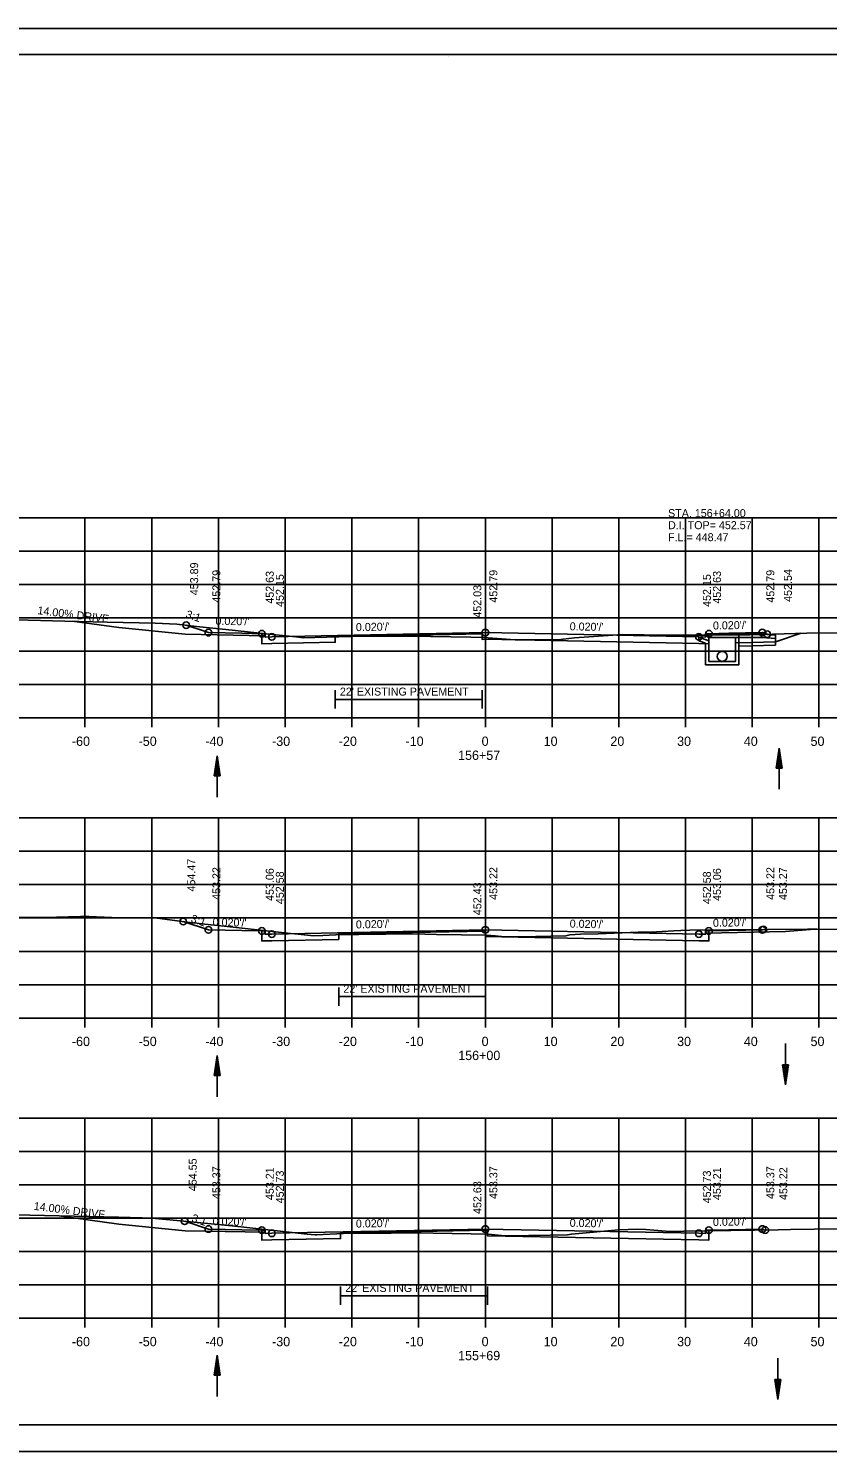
# Model space of a CAD drawing. Extents: x 1538688 to 1540766, y 656250 to 671912.
# Drawn here: x 1538789.7 to 1538909.5, y 666151.4 to 666364.8 of the extents above; entities that cross this region are included whole.
import ezdxf

# ---------------------------------------------------------------- set-up
doc = ezdxf.new("R2010")
doc.units = 0
for name, color, linetype in [('15', 7, 'Continuous'), ('16', 7, 'Continuous'), ('18', 7, 'Continuous'), ('20', 7, 'Continuous'), ('22', 7, 'Continuous'), ('26', 7, 'Continuous'), ('39', 7, 'Continuous'), ('40', 7, 'Continuous'), ('41', 7, 'Continuous'), ('42', 7, 'Continuous'), ('7', 7, 'Continuous'), ('Borings', 7, 'Continuous'), ('Horizontal Alignment', 7, 'Continuous'), ('RipRap', 7, 'Continuous'), ('Wall Heights', 7, 'Continuous')]:
    doc.layers.add(name, color=color, linetype=linetype)

msp = doc.modelspace()

# ---------------------------------------------------------------- linework, layer by layer
at = {"layer": '15'}
for p, q in [((1538817.56, 666252.74), (1538818.01, 666255.74)), ((1538818.46, 666252.74), (1538818.01, 666255.74)), ((1538901.74, 666253.91), (1538902.19, 666256.91)), ((1538901.82, 666253.91), (1538902.19, 666256.41)), ((1538901.89, 666253.91), (1538902.19, 666255.89)), ((1538902.64, 666253.91), (1538902.19, 666256.91)), ((1538902.57, 666253.91), (1538902.19, 666256.41)), ((1538902.49, 666253.91), (1538902.19, 666255.89)), ((1538817.64, 666252.74), (1538818.01, 666255.24)), ((1538817.71, 666252.74), (1538818.01, 666254.72)), ((1538817.79, 666252.74), (1538818.01, 666254.22)), ((1538817.87, 666252.74), (1538818.01, 666253.71)), ((1538818.39, 666252.74), (1538818.01, 666255.24)), ((1538818.31, 666252.74), (1538818.01, 666254.72)), ((1538818.23, 666252.74), (1538818.01, 666254.22)), ((1538818.16, 666252.74), (1538818.01, 666253.71)), ((1538901.74, 666253.91), (1538902.64, 666253.91)), ((1538901.97, 666253.91), (1538902.19, 666255.39)), ((1538902.05, 666253.91), (1538902.19, 666254.88)), ((1538902.12, 666253.91), (1538902.19, 666254.38)), ((1538902.42, 666253.91), (1538902.19, 666255.39)), ((1538902.34, 666253.91), (1538902.19, 666254.88)), ((1538902.26, 666253.91), (1538902.19, 666254.38)), ((1538817.56, 666252.74), (1538818.46, 666252.74)), ((1538817.94, 666252.74), (1538818.01, 666253.21)), ((1538818.08, 666252.74), (1538818.01, 666253.21)), ((1538817.56, 666207.82), (1538818.01, 666210.82)), ((1538818.46, 666207.82), (1538818.01, 666210.82)), ((1538817.64, 666207.82), (1538818.01, 666210.32)), ((1538817.71, 666207.82), (1538818.01, 666209.8)), ((1538817.79, 666207.82), (1538818.01, 666209.3)), ((1538817.87, 666207.82), (1538818.01, 666208.79)), ((1538818.39, 666207.82), (1538818.01, 666210.32)), ((1538818.31, 666207.82), (1538818.01, 666209.8)), ((1538818.23, 666207.82), (1538818.01, 666209.3)), ((1538818.16, 666207.82), (1538818.01, 666208.79)), ((1538902.69, 666209.42), (1538903.14, 666206.42)), ((1538903.59, 666209.42), (1538902.69, 666209.42)), ((1538902.76, 666209.42), (1538903.14, 666206.92)), ((1538902.84, 666209.42), (1538903.14, 666207.43)), ((1538902.92, 666209.42), (1538903.14, 666207.93)), ((1538902.99, 666209.42), (1538903.14, 666208.44)), ((1538903.07, 666209.42), (1538903.14, 666208.94)), ((1538903.59, 666209.42), (1538903.14, 666206.42)), ((1538903.28, 666209.42), (1538903.14, 666208.44)), ((1538903.44, 666209.42), (1538903.14, 666207.43)), ((1538903.51, 666209.42), (1538903.14, 666206.92)), ((1538903.36, 666209.42), (1538903.14, 666207.93)), ((1538903.21, 666209.42), (1538903.14, 666208.94)), ((1538817.56, 666207.82), (1538818.46, 666207.82)), ((1538817.94, 666207.82), (1538818.01, 666208.29)), ((1538818.08, 666207.82), (1538818.01, 666208.29)), ((1538817.56, 666162.9), (1538818.01, 666165.9)), ((1538818.46, 666162.9), (1538818.01, 666165.9)), ((1538817.64, 666162.9), (1538818.01, 666165.4)), ((1538817.71, 666162.9), (1538818.01, 666164.88)), ((1538817.79, 666162.9), (1538818.01, 666164.38)), ((1538817.87, 666162.9), (1538818.01, 666163.87)), ((1538818.39, 666162.9), (1538818.01, 666165.4)), ((1538818.31, 666162.9), (1538818.01, 666164.88)), ((1538818.23, 666162.9), (1538818.01, 666164.38)), ((1538818.16, 666162.9), (1538818.01, 666163.87)), ((1538817.56, 666162.9), (1538818.46, 666162.9)), ((1538817.94, 666162.9), (1538818.01, 666163.37)), ((1538818.08, 666162.9), (1538818.01, 666163.37)), ((1538901.54, 666162.26), (1538901.99, 666159.26)), ((1538902.44, 666162.26), (1538901.54, 666162.26)), ((1538901.62, 666162.26), (1538901.99, 666159.76)), ((1538901.69, 666162.26), (1538901.99, 666160.28)), ((1538901.77, 666162.26), (1538901.99, 666160.78)), ((1538901.85, 666162.26), (1538901.99, 666161.29)), ((1538901.92, 666162.26), (1538901.99, 666161.79)), ((1538902.44, 666162.26), (1538901.99, 666159.26)), ((1538902.14, 666162.26), (1538901.99, 666161.29)), ((1538902.29, 666162.26), (1538901.99, 666160.28)), ((1538902.37, 666162.26), (1538901.99, 666159.76)), ((1538902.22, 666162.26), (1538901.99, 666160.78)), ((1538902.06, 666162.26), (1538901.99, 666161.79))]:
    msp.add_line(p, q, dxfattribs=at)
at = {"layer": '16'}
for p, q in [((1538796.26, 666275.91), (1538803.23, 666274.96)), ((1538803.23, 666274.96), (1538813.18, 666273.96)), ((1538813.18, 666273.96), (1538825.18, 666273.72)), ((1538891.18, 666229.15), (1538903.18, 666229.39)), ((1538903.18, 666229.39), (1538907.5, 666229.77)), ((1538794.33, 666186.79), (1538803.23, 666185.54)), ((1538803.23, 666185.54), (1538813.18, 666184.55)), ((1538813.18, 666184.55), (1538825.18, 666184.31))]:
    msp.add_line(p, q, dxfattribs=at)
at = {"layer": '18'}
for points in [[(1538786.01, 666276.2), (1538795.15, 666275.93), (1538801.52, 666275.78), (1538808.68, 666275.61), (1538811.95, 666275.5), (1538814.88, 666275.12), (1538819.28, 666274.69), (1538825.8, 666274), (1538829.78, 666273.58), (1538830.94, 666273.45), (1538834.35, 666273.54), (1538836.24, 666273.59), (1538837.97, 666273.61), (1538846.95, 666273.7), (1538856, 666273.51), (1538857.89, 666273.47), (1538862.67, 666273.15), (1538862.97, 666273.14), (1538866.53, 666273.12), (1538868.6, 666273.11), (1538869.14, 666273.12), (1538869.83, 666273.24), (1538871.52, 666273.42), (1538878.75, 666273.95), (1538885.25, 666273.81), (1538889.63, 666273.85), (1538890.52, 666273.81), (1538891.48, 666273.81), (1538897.83, 666273.9), (1538906.37, 666274.14), (1538918.13, 666274.18)], [(1538782.15, 666231.6), (1538792.09, 666231.51), (1538797.51, 666231.64), (1538798.77, 666231.63), (1538803.36, 666231.45), (1538808.26, 666231.49), (1538813.12, 666230.87), (1538814.23, 666230.72), (1538814.92, 666230.66), (1538815.29, 666230.6), (1538816.14, 666230.53), (1538819.03, 666230.23), (1538828.98, 666229.13), (1538830.13, 666229), (1538832.42, 666228.74), (1538833.8, 666228.81), (1538836.73, 666228.94), (1538839.21, 666228.96), (1538847.36, 666229.04), (1538850.84, 666228.98), (1538858.33, 666228.85), (1538859.63, 666228.74), (1538861.04, 666228.61), (1538865.73, 666228.68), (1538870.24, 666228.76), (1538870.86, 666228.93), (1538872.46, 666228.99), (1538875.09, 666229.07), (1538881.1, 666229.33), (1538883.84, 666229.37), (1538886.42, 666229.5), (1538887.47, 666229.56), (1538888.84, 666229.61), (1538906.48, 666229.76), (1538906.74, 666229.77), (1538907.11, 666229.77), (1538907.93, 666229.77), (1538921.83, 666229.73)], [(1538785.4, 666186.99), (1538803.19, 666186.59), (1538806.75, 666186.5), (1538808.18, 666186.45), (1538811.92, 666186.1), (1538820.18, 666185.29), (1538831.47, 666184.04), (1538832.68, 666183.91), (1538832.85, 666183.92), (1538836.94, 666184.11), (1538844.05, 666184.19), (1538847.51, 666184.24), (1538856.03, 666184.1), (1538858.6, 666184.05), (1538860.59, 666183.85), (1538861.43, 666183.77), (1538867.89, 666183.89), (1538870.47, 666183.93), (1538871.08, 666184.04), (1538878.18, 666184.68), (1538880.98, 666184.78), (1538882.23, 666184.73), (1538885.83, 666184.41), (1538885.94, 666184.41), (1538885.96, 666184.41), (1538887.92, 666184.47), (1538902.06, 666184.68), (1538903.89, 666184.74), (1538918.12, 666184.94)]]:
    msp.add_lwpolyline(points, dxfattribs=at)
at = {"layer": '20'}
for points in [[(1538813.34, 666275.32), (1538816.67, 666274.21), (1538821.67, 666274.11), (1538824.67, 666274.05), (1538825.17, 666274.05), (1538825.18, 666273.55), (1538826.18, 666273.57), (1538858.18, 666274.21), (1538890.18, 666273.57), (1538891.18, 666273.55), (1538891.19, 666274.05), (1538891.69, 666274.05), (1538894.69, 666274.11), (1538899.69, 666274.21), (1538900.42, 666273.97)], [(1538812.9, 666230.9), (1538816.67, 666229.65), (1538821.67, 666229.55), (1538824.67, 666229.49), (1538825.17, 666229.49), (1538825.18, 666228.99), (1538826.18, 666229.01), (1538858.18, 666229.65), (1538890.18, 666229.01), (1538891.18, 666228.99), (1538891.19, 666229.49), (1538891.69, 666229.49), (1538894.69, 666229.55), (1538899.69, 666229.65), (1538899.86, 666229.7)], [(1538813.12, 666185.98), (1538816.67, 666184.8), (1538821.67, 666184.7), (1538824.67, 666184.64), (1538825.17, 666184.64), (1538825.18, 666184.14), (1538826.18, 666184.16), (1538858.18, 666184.8), (1538890.18, 666184.16), (1538891.18, 666184.14), (1538891.19, 666184.64), (1538891.69, 666184.64), (1538894.69, 666184.7), (1538899.69, 666184.8), (1538900.13, 666184.65)]]:
    msp.add_lwpolyline(points, dxfattribs=at)
at = {"layer": '22'}
for p, q in [((1538718.18, 666291.43), (1538998.18, 666291.43)), ((1538798.18, 666261.43), (1538798.18, 666291.43)), ((1538808.18, 666261.43), (1538808.18, 666291.43)), ((1538818.18, 666261.43), (1538818.18, 666291.43)), ((1538828.18, 666261.43), (1538828.18, 666291.43)), ((1538838.18, 666261.43), (1538838.18, 666291.43)), ((1538848.18, 666261.43), (1538848.18, 666291.43)), ((1538858.18, 666261.43), (1538858.18, 666291.43)), ((1538868.18, 666261.43), (1538868.18, 666291.43)), ((1538878.18, 666261.43), (1538878.18, 666291.43)), ((1538888.18, 666261.43), (1538888.18, 666291.43)), ((1538898.18, 666261.43), (1538898.18, 666291.43)), ((1538908.18, 666261.43), (1538908.18, 666291.43)), ((1538718.18, 666286.43), (1538998.18, 666286.43)), ((1538718.18, 666281.43), (1538998.18, 666281.43)), ((1538718.18, 666276.43), (1538998.18, 666276.43)), ((1538718.18, 666271.43), (1538998.18, 666271.43)), ((1538718.18, 666266.43), (1538998.18, 666266.43)), ((1538718.18, 666261.43), (1538998.18, 666261.43)), ((1538718.18, 666246.43), (1538998.18, 666246.43)), ((1538798.18, 666216.43), (1538798.18, 666246.43)), ((1538808.18, 666216.43), (1538808.18, 666246.43)), ((1538818.18, 666216.43), (1538818.18, 666246.43)), ((1538828.18, 666216.43), (1538828.18, 666246.43)), ((1538838.18, 666216.43), (1538838.18, 666246.43)), ((1538848.18, 666216.43), (1538848.18, 666246.43)), ((1538858.18, 666216.43), (1538858.18, 666246.43)), ((1538868.18, 666216.43), (1538868.18, 666246.43)), ((1538878.18, 666216.43), (1538878.18, 666246.43)), ((1538888.18, 666216.43), (1538888.18, 666246.43)), ((1538898.18, 666216.43), (1538898.18, 666246.43)), ((1538908.18, 666216.43), (1538908.18, 666246.43)), ((1538718.18, 666241.43), (1538998.18, 666241.43)), ((1538718.18, 666236.43), (1538998.18, 666236.43)), ((1538718.18, 666231.43), (1538998.18, 666231.43)), ((1538718.18, 666226.43), (1538998.18, 666226.43)), ((1538718.18, 666221.43), (1538998.18, 666221.43)), ((1538718.18, 666216.43), (1538998.18, 666216.43)), ((1538718.18, 666201.43), (1538998.18, 666201.43)), ((1538798.18, 666171.43), (1538798.18, 666201.43)), ((1538808.18, 666171.43), (1538808.18, 666201.43)), ((1538818.18, 666171.43), (1538818.18, 666201.43)), ((1538828.18, 666171.43), (1538828.18, 666201.43)), ((1538838.18, 666171.43), (1538838.18, 666201.43)), ((1538848.18, 666171.43), (1538848.18, 666201.43)), ((1538858.18, 666171.43), (1538858.18, 666201.43)), ((1538868.18, 666171.43), (1538868.18, 666201.43)), ((1538878.18, 666171.43), (1538878.18, 666201.43)), ((1538888.18, 666171.43), (1538888.18, 666201.43)), ((1538898.18, 666171.43), (1538898.18, 666201.43)), ((1538908.18, 666171.43), (1538908.18, 666201.43)), ((1538718.18, 666196.43), (1538998.18, 666196.43)), ((1538718.18, 666191.43), (1538998.18, 666191.43)), ((1538718.18, 666186.43), (1538998.18, 666186.43)), ((1538718.18, 666181.43), (1538998.18, 666181.43)), ((1538718.18, 666176.43), (1538998.18, 666176.43)), ((1538718.18, 666171.43), (1538998.18, 666171.43))]:
    msp.add_line(p, q, dxfattribs=at)
at = {"layer": '26'}
for p, q in [((1538687.78, 666364.78), (1539021.11, 666364.78)), ((1538687.78, 666151.45), (1539021.11, 666151.45))]:
    msp.add_line(p, q, dxfattribs=at)
msp.add_lwpolyline([(1538687.77, 666364.78), (1539021.11, 666364.78), (1539021.11, 666151.45), (1538687.77, 666151.45)], close=True, dxfattribs=at)
for centre in [(1538813.34, 666275.32), (1538816.67, 666274.21), (1538858.18, 666274.21), (1538899.69, 666274.21), (1538824.67, 666274.05), (1538826.18, 666273.57), (1538890.18, 666273.57), (1538891.69, 666274.05), (1538900.42, 666273.97), (1538812.9, 666230.9), (1538816.67, 666229.65), (1538824.67, 666229.49), (1538858.18, 666229.65), (1538891.69, 666229.49), (1538899.69, 666229.65), (1538899.86, 666229.7), (1538826.18, 666229.01), (1538890.18, 666229.01), (1538813.12, 666185.98), (1538816.67, 666184.8), (1538824.67, 666184.64), (1538858.18, 666184.8), (1538891.69, 666184.64), (1538899.69, 666184.8), (1538900.13, 666184.65), (1538826.18, 666184.16), (1538890.18, 666184.16)]:
    msp.add_circle(centre, 0.5, dxfattribs=at)
at = {"layer": '39'}
for p, q in [((1538890.18, 666273.52), (1538891.68, 666273)), ((1538890.18, 666273.52), (1538891.68, 666273)), ((1538890.18, 666272.99), (1538891.18, 666272.64)), ((1538890.18, 666272.99), (1538891.18, 666272.64)), ((1538891.18, 666272.5), (1538891.18, 666272.64)), ((1538891.18, 666272.5), (1538891.18, 666272.64)), ((1538891.34, 666273.83), (1538891.43, 666274)), ((1538891.34, 666273.83), (1538891.43, 666274)), ((1538891.34, 666273.83), (1538891.68, 666273.5)), ((1538891.34, 666273.83), (1538891.68, 666273.5)), ((1538896.18, 666274), (1538891.43, 666274)), ((1538896.18, 666274), (1538891.43, 666274)), ((1538895.68, 666273.5), (1538891.68, 666273.5)), ((1538895.68, 666273.5), (1538891.68, 666273.5)), ((1538891.68, 666272.5), (1538891.68, 666273)), ((1538891.68, 666272.5), (1538891.68, 666273)), ((1538895.68, 666272.5), (1538895.68, 666273.5)), ((1538896.18, 666272.5), (1538896.18, 666274)), ((1538899.66, 666274), (1538901.69, 666273.85)), ((1538899.69, 666273.5), (1538901.68, 666273.35)), ((1538901.64, 666272.85), (1538905.53, 666274.14)), ((1538818.01, 666249.55), (1538818.01, 666255.74)), ((1538902.19, 666250.72), (1538902.19, 666256.91)), ((1538818.01, 666204.63), (1538818.01, 666210.82)), ((1538903.14, 666212.6), (1538903.14, 666206.42)), ((1538818.01, 666159.71), (1538818.01, 666165.9)), ((1538901.99, 666165.45), (1538901.99, 666159.26))]:
    msp.add_line(p, q, dxfattribs=at)
for points in [[(1538890.18, 666272.99), (1538890.18, 666273.52)], [(1538890.18, 666272.99), (1538890.18, 666273.52)], [(1538895.68, 666273.5), (1538898.18, 666273.5), (1538899.69, 666273.5)], [(1538895.68, 666272.66), (1538898.09, 666272.74), (1538901.64, 666272.85)], [(1538896.18, 666274), (1538898.18, 666274), (1538899.69, 666274)], [(1538896.18, 666272.18), (1538898.11, 666272.24), (1538901.66, 666272.35), (1538901.68, 666273.85)], [(1538896.18, 666272.5), (1538896.18, 666269.4), (1538893.68, 666269.4), (1538891.18, 666269.4), (1538891.18, 666272.5)], [(1538895.68, 666272.5), (1538895.68, 666269.9), (1538893.68, 666269.9), (1538891.68, 666269.9), (1538891.68, 666272.5)]]:
    msp.add_lwpolyline(points, dxfattribs=at)
msp.add_circle((1538893.68, 666270.65), 0.75, dxfattribs=at)
at = {"layer": '7'}
for p, q in [((1538835.68, 666265.59), (1538835.68, 666262.84)), ((1538857.68, 666264.21), (1538835.68, 666264.21)), ((1538857.68, 666265.59), (1538857.68, 666262.84)), ((1538836.2, 666221.03), (1538836.2, 666218.28)), ((1538858.2, 666219.66), (1538836.2, 666219.66)), ((1538858.2, 666221.03), (1538858.2, 666218.28)), ((1538836.48, 666176.19), (1538836.48, 666173.44)), ((1538858.48, 666174.81), (1538836.48, 666174.81)), ((1538858.48, 666176.19), (1538858.48, 666173.44))]:
    msp.add_line(p, q, dxfattribs=at)
at = {"layer": 'Borings'}
for p, q in [((1538718.18, 666261.43), (1538998.18, 666261.43)), ((1538798.18, 666260.03), (1538798.18, 666261.43)), ((1538808.18, 666260.03), (1538808.18, 666261.43)), ((1538818.18, 666260.03), (1538818.18, 666261.43)), ((1538828.18, 666260.03), (1538828.18, 666261.43)), ((1538838.18, 666260.03), (1538838.18, 666261.43)), ((1538848.18, 666260.03), (1538848.18, 666261.43)), ((1538858.18, 666260.03), (1538858.18, 666261.43)), ((1538868.18, 666260.03), (1538868.18, 666261.43)), ((1538878.18, 666260.03), (1538878.18, 666261.43)), ((1538888.18, 666260.03), (1538888.18, 666261.43)), ((1538898.18, 666260.03), (1538898.18, 666261.43)), ((1538908.18, 666260.03), (1538908.18, 666261.43)), ((1538718.18, 666216.43), (1538998.18, 666216.43)), ((1538798.18, 666215.03), (1538798.18, 666216.43)), ((1538808.18, 666215.03), (1538808.18, 666216.43)), ((1538818.18, 666215.03), (1538818.18, 666216.43)), ((1538828.18, 666215.03), (1538828.18, 666216.43)), ((1538838.18, 666215.03), (1538838.18, 666216.43)), ((1538848.18, 666215.03), (1538848.18, 666216.43)), ((1538858.18, 666215.03), (1538858.18, 666216.43)), ((1538868.18, 666215.03), (1538868.18, 666216.43)), ((1538878.18, 666215.03), (1538878.18, 666216.43)), ((1538888.18, 666215.03), (1538888.18, 666216.43)), ((1538898.18, 666215.03), (1538898.18, 666216.43)), ((1538908.18, 666215.03), (1538908.18, 666216.43)), ((1538718.18, 666171.43), (1538998.18, 666171.43)), ((1538798.18, 666170.03), (1538798.18, 666171.43)), ((1538808.18, 666170.03), (1538808.18, 666171.43)), ((1538818.18, 666170.03), (1538818.18, 666171.43)), ((1538828.18, 666170.03), (1538828.18, 666171.43)), ((1538838.18, 666170.03), (1538838.18, 666171.43)), ((1538848.18, 666170.03), (1538848.18, 666171.43)), ((1538858.18, 666170.03), (1538858.18, 666171.43)), ((1538868.18, 666170.03), (1538868.18, 666171.43)), ((1538878.18, 666170.03), (1538878.18, 666171.43)), ((1538888.18, 666170.03), (1538888.18, 666171.43)), ((1538898.18, 666170.03), (1538898.18, 666171.43)), ((1538908.18, 666170.03), (1538908.18, 666171.43))]:
    msp.add_line(p, q, dxfattribs=at)
at = {"layer": 'RipRap'}
for p, q in [((1538700.18, 666360.89), (1539016.36, 666360.89)), ((1538852.7, 666360.63), (1538852.7, 666360.63)), ((1538852.7, 666360.63), (1538852.7, 666360.63)), ((1539016.36, 666155.43), (1538700.18, 666155.43))]:
    msp.add_line(p, q, dxfattribs=at)
at = {"layer": 'Wall Heights'}
for points in [[(1538891.69, 666274.05), (1538891.69, 666272.55), (1538890.18, 666272.57), (1538858.18, 666273.21), (1538857.69, 666273.2), (1538857.69, 666274.04), (1538835.69, 666273.6), (1538835.69, 666272.76), (1538826.18, 666272.57), (1538824.67, 666272.55), (1538824.67, 666274.05)], [(1538891.69, 666229.49), (1538891.69, 666227.99), (1538890.18, 666228.01), (1538858.21, 666228.65), (1538858.21, 666229.48), (1538858.18, 666229.48), (1538836.21, 666229.04), (1538836.21, 666228.21), (1538826.18, 666228.01), (1538824.67, 666227.99), (1538824.67, 666229.49)], [(1538891.69, 666184.64), (1538891.69, 666183.14), (1538890.18, 666183.16), (1538858.49, 666183.79), (1538858.49, 666184.62), (1538858.18, 666184.63), (1538836.49, 666184.2), (1538836.49, 666183.37), (1538826.18, 666183.16), (1538824.67, 666183.14), (1538824.67, 666184.64)]]:
    msp.add_lwpolyline(points, dxfattribs=at)

# ---------------------------------------------------------------- texts
at = {"layer": '16'}
for p in [(1538791.01, 666276.99), (1538790.45, 666187.69)]:
    msp.add_text('14.00% DRIVE', height=1.2, rotation=352.879, dxfattribs=at).set_placement(p)
at = {"layer": '40'}
for s, p in [('STA. 156+64.00', (1538885.56, 666291.52)), ('D.I. TOP= 452.57', (1538885.56, 666289.72)), ('F.L.= 448.47', (1538885.56, 666287.92))]:
    msp.add_text(s, height=1.2, dxfattribs=at).set_placement(p)
at = {"layer": '41'}
for s, p in [('453.89', (1538815.14, 666279.82)), ('452.79', (1538818.47, 666278.71)), ('452.63', (1538826.47, 666278.55)), ('452.79', (1538859.98, 666278.71)), ('452.63', (1538893.49, 666278.55)), ('452.79', (1538901.49, 666278.71)), ('452.54', (1538904.12, 666278.82)), ('452.15', (1538827.98, 666278.07)), ('452.03', (1538857.58, 666276.45)), ('452.15', (1538891.98, 666278.07)), ('454.47', (1538814.7, 666235.4)), ('453.22', (1538818.47, 666234.15)), ('453.06', (1538826.47, 666233.99)), ('453.22', (1538859.98, 666234.15)), ('453.06', (1538893.49, 666233.99)), ('453.22', (1538901.49, 666234.15)), ('453.27', (1538903.39, 666234.12)), ('452.58', (1538827.98, 666233.51)), ('452.43', (1538857.58, 666231.85)), ('452.58', (1538891.98, 666233.51)), ('454.55', (1538814.92, 666190.48)), ('453.37', (1538818.47, 666189.3)), ('453.21', (1538826.47, 666189.14)), ('453.37', (1538859.98, 666189.3)), ('453.21', (1538893.49, 666189.14)), ('453.37', (1538901.49, 666189.3)), ('453.22', (1538903.44, 666189.15)), ('452.73', (1538827.98, 666188.66)), ('452.63', (1538857.58, 666187.06)), ('452.73', (1538891.98, 666188.66))]:
    msp.add_text(s, height=1.2, rotation=90, dxfattribs=at).set_placement(p)
at = {"layer": '42'}
for s, rotation, p in [('3:1', 341.5651, (1538813.18, 666276.48)), ("0.020'/'", 358.8542, (1538817.72, 666275.39)), ("0.020'/'", 1.1458, (1538838.79, 666274.43)), ("0.020'/'", 358.8542, (1538870.81, 666274.56)), ("0.020'/'", 1.1458, (1538892.3, 666274.67)), ('3:1', 341.5651, (1538813.94, 666230.85)), ("0.020'/'", 358.8542, (1538817.3, 666230.23)), ("0.020'/'", 1.1458, (1538838.79, 666229.86)), ("0.020'/'", 358.8542, (1538870.81, 666229.99)), ("0.020'/'", 1.1458, (1538892.3, 666230.1)), ('3:1', 341.5651, (1538814.05, 666185.96)), ("0.020'/'", 358.8542, (1538817.3, 666185.38)), ("0.020'/'", 1.1458, (1538838.79, 666185.01)), ("0.020'/'", 358.8542, (1538870.81, 666185.14)), ("0.020'/'", 1.1458, (1538892.3, 666185.25))]:
    msp.add_text(s, height=1.2, rotation=rotation, dxfattribs=at).set_placement(p)
at = {"layer": '7'}
for p in [(1538836.38, 666264.77), (1538836.9, 666220.22), (1538837.19, 666175.37)]:
    msp.add_text("22' EXISTING PAVEMENT", height=1.2, dxfattribs=at).set_placement(p)
at = {"layer": 'Horizontal Alignment'}
for s, p in [('-60', (1538796.22, 666257.23)), ('-50', (1538806.22, 666257.23)), ('-40', (1538816.22, 666257.23)), ('-30', (1538826.22, 666257.23)), ('-20', (1538836.22, 666257.23)), ('-10', (1538846.22, 666257.23)), ('0', (1538857.62, 666257.23)), ('10', (1538866.92, 666257.23)), ('20', (1538876.92, 666257.23)), ('30', (1538886.92, 666257.23)), ('40', (1538896.92, 666257.23)), ('50', (1538906.92, 666257.23)), ('156+57', (1538854.1, 666255.13)), ('-60', (1538796.22, 666212.23)), ('-50', (1538806.22, 666212.23)), ('-40', (1538816.22, 666212.23)), ('-30', (1538826.22, 666212.23)), ('-20', (1538836.22, 666212.23)), ('-10', (1538846.22, 666212.23)), ('0', (1538857.62, 666212.23)), ('10', (1538866.92, 666212.23)), ('20', (1538876.92, 666212.23)), ('30', (1538886.92, 666212.23)), ('40', (1538896.92, 666212.23)), ('50', (1538906.92, 666212.23)), ('156+00', (1538854.12, 666210.13)), ('-60', (1538796.22, 666167.23)), ('-50', (1538806.22, 666167.23)), ('-40', (1538816.22, 666167.23)), ('-30', (1538826.22, 666167.23)), ('-20', (1538836.22, 666167.23)), ('-10', (1538846.22, 666167.23)), ('0', (1538857.62, 666167.23)), ('10', (1538866.92, 666167.23)), ('20', (1538876.92, 666167.23)), ('30', (1538886.92, 666167.23)), ('40', (1538896.92, 666167.23)), ('50', (1538906.92, 666167.23)), ('155+69', (1538854.1, 666165.13))]:
    msp.add_text(s, height=1.4, dxfattribs=at).set_placement(p)

doc.saveas('drawing.dxf')
